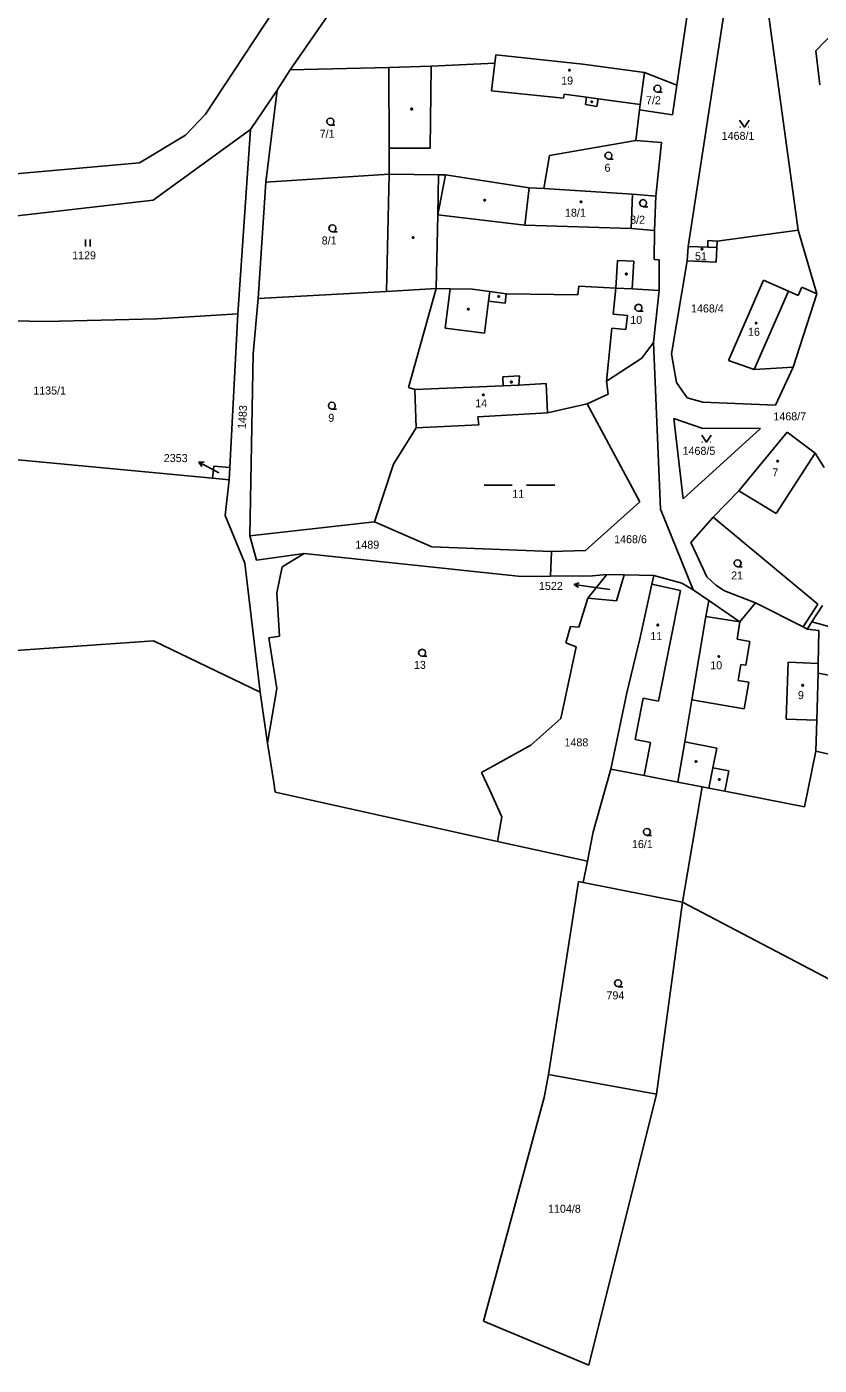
# Model space of a CAD drawing. Extents: x -852001 to -842497, y -1063614 to -1052182.
# Drawn here: x -850781 to -850612.7, y -1053765.9 to -1053481.6 of the extents above; entities that cross this region are included whole.
import ezdxf

# ---------------------------------------------------------------- set-up
doc = ezdxf.new("R2010")
doc.units = 0
for name, color, linetype in [('Default', 7, 'Continuous'), ('KN_HRANICE', 7, 'Continuous'), ('KN_KULTURY', 7, 'Continuous'), ('KN_PARCELY', 7, 'Continuous'), ('KN_SLUCKY', 7, 'Continuous')]:
    doc.layers.add(name, color=color, linetype=linetype)

# ---------------------------------------------------------------- blocks, each defined once
blk = doc.blocks.new('304')
at = {"layer": 'Default'}
blk.add_lwpolyline([(0, 0), (-0.38, 0.1), (-0.65, 0.37), (-0.75, 0.74), (-0.65, 1.11), (-0.38, 1.38), (-0.01, 1.48), (0.36, 1.38), (0.63, 1.11), (0.73, 0.73), (0.63, 0.35), (0.36, 0.08), (-0.02, -0.02), (0.98, -0.02)], dxfattribs=at)
blk = doc.blocks.new('306')
at = {"layer": 'Default'}
for p, q in [((-0.5, 1.5), (-0.5, 0)), ((0.5, 0), (0.5, 1.5))]:
    blk.add_line(p, q, dxfattribs=at)
blk = doc.blocks.new('314')
at = {"layer": 'Default'}
for p, q in [((-0.95, 0), (-0.85, 0)), ((0.85, 0), (0.95, 0))]:
    blk.add_line(p, q, dxfattribs=at)
blk.add_lwpolyline([(-1, 1.5), (0, 0), (1, 1.5)], dxfattribs=at)
blk = doc.blocks.new('803')
at = {"layer": 'Default'}
for p, q in [((-7.5, 0), (-1.5, 0)), ((1.5, 0), (7.5, 0))]:
    blk.add_line(p, q, dxfattribs=at)
blk = doc.blocks.new('10292')
at = {"layer": 'Default'}
blk.add_line((0, 3), (0, 0), dxfattribs=at)
blk.add_lwpolyline([(-0.5, 2), (0, 3), (0.5, 2)], dxfattribs=at)
blk = doc.blocks.new('402')
at = {"layer": 'Default'}
blk.add_lwpolyline([(0.09, 0.15), (0.18, 0), (0.09, -0.15), (-0.09, -0.15), (-0.18, 0), (-0.09, 0.15), (0.09, 0.15)], dxfattribs=at)

msp = doc.modelspace()

# ---------------------------------------------------------------- linework, layer by layer
at = {"layer": 'KN_HRANICE'}
for p, q in [((-850725.03, -1053490.78), (-850702.85, -1053458.77)), ((-850720.89, -1053466.48), (-850743, -1053500.2)), ((-850638.85, -1053466.06), (-850642.9, -1053493.99)), ((-850624.21, -1053473.39), (-850617.15, -1053524.78)), ((-850632.5, -1053476.14), (-850640.52, -1053528.25)), ((-850609.81, -1053482.98), (-850613.39, -1053486.7)), ((-850681.39, -1053487.58), (-850681.6, -1053489.34)), ((-850662.9, -1053489.55), (-850681.39, -1053487.58)), ((-850613.39, -1053486.7), (-850612.58, -1053493.95)), ((-850727.77, -1053495.08), (-850725.03, -1053490.78)), ((-850704.11, -1053490.22), (-850725.03, -1053490.78)), ((-850695.07, -1053489.98), (-850704.11, -1053490.22)), ((-850704, -1053507.36), (-850704.11, -1053490.22)), ((-850695.07, -1053489.98), (-850681.6, -1053489.34)), ((-850649.81, -1053491.29), (-850662.9, -1053489.55)), ((-850650.72, -1053498.08), (-850649.81, -1053491.29)), ((-850649.81, -1053491.29), (-850642.9, -1053493.99)), ((-850733.45, -1053503.39), (-850727.77, -1053495.08)), ((-850727.77, -1053495.08), (-850730.2, -1053514.63)), ((-850642.9, -1053493.99), (-850643.82, -1053500.3)), ((-850651.6, -1053505.78), (-850650.88, -1053499.27)), ((-850650.88, -1053499.27), (-850650.72, -1053498.08)), ((-850650.88, -1053499.27), (-850643.82, -1053500.3)), ((-850743, -1053500.2), (-850747.27, -1053504.66)), ((-850747.27, -1053504.66), (-850757.05, -1053510.53)), ((-850754.1, -1053518.43), (-850733.45, -1053503.39)), ((-850736.12, -1053542.56), (-850733.45, -1053503.39)), ((-850703.97, -1053512.92), (-850704, -1053507.36)), ((-850651.6, -1053505.78), (-850669.93, -1053508.92)), ((-850646.16, -1053506.15), (-850651.6, -1053505.78)), ((-850647.39, -1053517.55), (-850646.16, -1053506.15)), ((-850757.05, -1053510.53), (-850788.26, -1053513.24)), ((-850669.93, -1053508.92), (-850671.13, -1053515.98)), ((-850730.2, -1053514.63), (-850703.97, -1053512.92)), ((-850703.97, -1053512.92), (-850704.59, -1053537.84)), ((-850703.97, -1053512.92), (-850693.51, -1053513.03)), ((-850693.51, -1053513.03), (-850692.06, -1053513.04)), ((-850692.06, -1053513.04), (-850674.27, -1053515.78)), ((-850730.2, -1053514.63), (-850731.83, -1053539.3)), ((-850674.27, -1053515.78), (-850671.13, -1053515.98)), ((-850671.13, -1053515.98), (-850652.32, -1053517.19)), ((-850787.65, -1053522.28), (-850754.1, -1053518.43)), ((-850652.32, -1053517.19), (-850652.6, -1053524.47)), ((-850652.32, -1053517.19), (-850647.39, -1053517.55)), ((-850647.68, -1053524.87), (-850647.39, -1053517.55)), ((-850652.6, -1053524.47), (-850647.68, -1053524.87)), ((-850647.72, -1053531.05), (-850647.68, -1053524.87)), ((-850634.37, -1053527.13), (-850617.15, -1053524.78)), ((-850617.15, -1053524.78), (-850613.2, -1053538.34)), ((-850636.31, -1053527.03), (-850636.37, -1053528.43)), ((-850636.31, -1053527.03), (-850634.37, -1053527.13)), ((-850634.44, -1053528.52), (-850634.37, -1053527.13)), ((-850640.72, -1053531.35), (-850640.52, -1053528.25)), ((-850640.52, -1053528.25), (-850636.37, -1053528.43)), ((-850634.59, -1053531.62), (-850634.44, -1053528.52)), ((-850646.65, -1053531.12), (-850647.72, -1053531.05)), ((-850646.66, -1053537.61), (-850646.65, -1053531.12)), ((-850644.03, -1053551.05), (-850640.72, -1053531.35)), ((-850640.72, -1053531.35), (-850634.59, -1053531.62)), ((-850624.54, -1053535.45), (-850631.98, -1053552.46)), ((-850619.2, -1053537.77), (-850624.54, -1053535.45)), ((-850731.83, -1053539.3), (-850704.59, -1053537.84)), ((-850704.59, -1053537.84), (-850694.04, -1053537.19)), ((-850694.04, -1053537.19), (-850699.87, -1053558.24)), ((-850694.04, -1053537.19), (-850691.08, -1053537.27)), ((-850691.08, -1053537.27), (-850686.4, -1053537.34)), ((-850686.4, -1053537.34), (-850682.66, -1053537.85)), ((-850682.66, -1053537.85), (-850679.16, -1053538.32)), ((-850679.16, -1053538.32), (-850663.91, -1053538.55)), ((-850663.91, -1053538.55), (-850663.74, -1053536.68)), ((-850655.85, -1053537.11), (-850663.74, -1053536.68)), ((-850655.85, -1053537.11), (-850656.41, -1053542.64)), ((-850652.38, -1053537.3), (-850655.85, -1053537.11)), ((-850646.66, -1053537.61), (-850652.38, -1053537.3)), ((-850647.89, -1053548.68), (-850646.66, -1053537.61)), ((-850617.16, -1053538.65), (-850619.2, -1053537.77)), ((-850613.2, -1053538.34), (-850618.2, -1053553.93)), ((-850616.4, -1053536.9), (-850617.16, -1053538.65)), ((-850616.4, -1053536.9), (-850613.2, -1053538.34)), ((-850731.83, -1053539.3), (-850732.9, -1053551.1)), ((-850776.98, -1053544.19), (-850811.29, -1053543.49)), ((-850753.31, -1053543.66), (-850776.98, -1053544.19)), ((-850736.12, -1053542.56), (-850753.31, -1053543.66)), ((-850737.82, -1053575.23), (-850736.12, -1053542.56)), ((-850656.41, -1053542.64), (-850653.42, -1053542.95)), ((-850653.42, -1053542.95), (-850653.72, -1053545.93)), ((-850657.85, -1053556.86), (-850656.71, -1053545.63)), ((-850653.72, -1053545.93), (-850656.71, -1053545.63)), ((-850650.36, -1053552.02), (-850647.89, -1053548.68)), ((-850647.89, -1053548.68), (-850646.41, -1053584.08)), ((-850732.9, -1053551.1), (-850733.6, -1053589.76)), ((-850657.85, -1053556.86), (-850650.36, -1053552.02)), ((-850643.02, -1053557.16), (-850644.03, -1053551.05)), ((-850631.98, -1053552.46), (-850626.47, -1053554.4)), ((-850626.47, -1053554.4), (-850618.2, -1053553.93)), ((-850618.2, -1053553.93), (-850621.95, -1053561.95)), ((-850699.87, -1053558.24), (-850698.57, -1053558.66)), ((-850698.25, -1053566.82), (-850698.57, -1053558.66)), ((-850657.53, -1053559.65), (-850657.85, -1053556.86)), ((-850640.75, -1053560.43), (-850643.02, -1053557.16)), ((-850661.96, -1053561.72), (-850670.36, -1053563.6)), ((-850661.96, -1053561.72), (-850657.53, -1053559.65)), ((-850650.8, -1053582.53), (-850661.96, -1053561.72)), ((-850637.41, -1053561.33), (-850640.75, -1053560.43)), ((-850621.95, -1053561.95), (-850637.41, -1053561.33)), ((-850670.36, -1053563.6), (-850685.16, -1053564.49)), ((-850685.16, -1053564.49), (-850684.99, -1053566.13)), ((-850643.55, -1053564.8), (-850637.64, -1053566.88)), ((-850641.59, -1053581.86), (-850643.55, -1053564.8)), ((-850703.1, -1053574.48), (-850698.25, -1053566.82)), ((-850698.25, -1053566.82), (-850684.99, -1053566.13)), ((-850625.16, -1053566.93), (-850641.59, -1053581.86)), ((-850637.64, -1053566.88), (-850625.16, -1053566.93)), ((-850819.36, -1053570.11), (-850741.49, -1053577.51)), ((-850629.75, -1053580.2), (-850619.47, -1053567.69)), ((-850619.47, -1053567.69), (-850613.54, -1053572.2)), ((-850613.54, -1053572.2), (-850611.6, -1053575.23)), ((-850741.22, -1053574.92), (-850741.49, -1053577.51)), ((-850737.82, -1053575.23), (-850741.22, -1053574.92)), ((-850737.96, -1053577.85), (-850737.82, -1053575.23)), ((-850707.14, -1053586.78), (-850703.1, -1053574.48)), ((-850741.49, -1053577.51), (-850737.96, -1053577.85)), ((-850737.96, -1053577.85), (-850738.81, -1053585.42)), ((-850635.17, -1053585.8), (-850629.75, -1053580.2)), ((-850662.32, -1053592.86), (-850650.8, -1053582.53)), ((-850646.41, -1053584.08), (-850639.44, -1053601.2)), ((-850738.81, -1053585.42), (-850734.66, -1053595.56)), ((-850733.6, -1053589.76), (-850707.14, -1053586.78)), ((-850707.14, -1053586.78), (-850694.94, -1053592.06)), ((-850639.95, -1053591.18), (-850635.17, -1053585.8)), ((-850635.17, -1053585.8), (-850612.97, -1053604.25)), ((-850733.6, -1053589.76), (-850732.16, -1053594.91)), ((-850694.94, -1053592.06), (-850669.55, -1053593.05)), ((-850669.55, -1053593.05), (-850669.76, -1053598.34)), ((-850669.55, -1053593.05), (-850662.32, -1053592.86)), ((-850639.95, -1053591.18), (-850638.77, -1053593.71)), ((-850734.66, -1053595.56), (-850731.37, -1053622.93)), ((-850722.02, -1053593.47), (-850732.16, -1053594.91)), ((-850726.71, -1053596.35), (-850722.02, -1053593.47)), ((-850722.02, -1053593.47), (-850675.99, -1053598.41)), ((-850638.77, -1053593.71), (-850636.55, -1053598.46)), ((-850727.84, -1053601.86), (-850726.71, -1053596.35)), ((-850675.99, -1053598.41), (-850669.76, -1053598.34)), ((-850669.76, -1053598.34), (-850660.81, -1053598.24)), ((-850661.81, -1053603.01), (-850657.8, -1053597.97)), ((-850660.81, -1053598.24), (-850657.8, -1053597.97)), ((-850657.8, -1053597.97), (-850654.08, -1053598.05)), ((-850655.76, -1053603.54), (-850654.08, -1053598.05)), ((-850654.08, -1053598.05), (-850647.82, -1053598.17)), ((-850648.23, -1053600.03), (-850647.82, -1053598.17)), ((-850647.82, -1053598.17), (-850641.87, -1053599.8)), ((-850636.55, -1053598.46), (-850634.65, -1053600.2)), ((-850650.71, -1053611.35), (-850648.23, -1053600.03)), ((-850641.87, -1053599.8), (-850639.44, -1053601.2)), ((-850636.16, -1053603.46), (-850639.44, -1053601.2)), ((-850634.65, -1053600.2), (-850632.83, -1053601.39)), ((-850632.83, -1053601.39), (-850626.23, -1053603.99)), ((-850727.27, -1053611.05), (-850727.84, -1053601.86)), ((-850663.74, -1053609.12), (-850661.81, -1053603.01)), ((-850661.81, -1053603.01), (-850655.76, -1053603.54)), ((-850636.73, -1053606.84), (-850636.16, -1053603.46)), ((-850629.52, -1053608.02), (-850636.16, -1053603.46)), ((-850629.52, -1053608.02), (-850626.23, -1053603.99)), ((-850626.23, -1053603.99), (-850616.11, -1053609.04)), ((-850612.97, -1053604.25), (-850616.11, -1053609.04)), ((-850639.73, -1053624.59), (-850636.73, -1053606.84)), ((-850666.46, -1053612.48), (-850665.53, -1053608.97)), ((-850665.53, -1053608.97), (-850663.74, -1053609.12)), ((-850616.11, -1053609.04), (-850615.28, -1053609.57)), ((-850614.24, -1053607.97), (-850615.28, -1053609.57)), ((-850615.28, -1053609.57), (-850612.79, -1053609.83)), ((-850605.98, -1053610.26), (-850614.24, -1053607.97)), ((-850612.9, -1053616.89), (-850612.79, -1053609.83)), ((-850754.03, -1053612.06), (-850790.19, -1053614.59)), ((-850731.37, -1053622.93), (-850754.03, -1053612.06)), ((-850727.27, -1053611.05), (-850729.55, -1053611.4)), ((-850729.55, -1053611.4), (-850727.84, -1053622.2)), ((-850664.31, -1053613.34), (-850666.46, -1053612.48)), ((-850653.56, -1053623.08), (-850650.71, -1053611.35)), ((-850667.53, -1053628.53), (-850664.31, -1053613.34)), ((-850619.29, -1053616.58), (-850619.67, -1053628.68)), ((-850612.9, -1053616.89), (-850619.29, -1053616.58)), ((-850612.93, -1053618.93), (-850612.9, -1053616.89)), ((-850612.93, -1053618.93), (-850613.21, -1053628.86)), ((-850599.25, -1053621.58), (-850612.93, -1053618.93)), ((-850731.37, -1053622.93), (-850729.84, -1053633.77)), ((-850727.84, -1053622.2), (-850729.84, -1053633.77)), ((-850656.92, -1053639.28), (-850653.56, -1053623.08)), ((-850641.24, -1053633.53), (-850639.73, -1053624.59)), ((-850673.91, -1053634.19), (-850667.53, -1053628.53)), ((-850619.67, -1053628.68), (-850613.21, -1053628.86)), ((-850613.21, -1053628.86), (-850613.39, -1053635.48)), ((-850729.84, -1053633.77), (-850728.5, -1053642.15)), ((-850684.37, -1053639.99), (-850673.91, -1053634.19)), ((-850642.68, -1053642.07), (-850641.24, -1053633.53)), ((-850615.84, -1053647.32), (-850613.39, -1053635.48)), ((-850613.39, -1053635.48), (-850581.18, -1053642.71)), ((-850682.73, -1053643.61), (-850684.37, -1053639.99)), ((-850660.67, -1053652.62), (-850656.92, -1053639.28)), ((-850656.92, -1053639.28), (-850649.89, -1053640.66)), ((-850649.89, -1053640.66), (-850642.68, -1053642.07)), ((-850728.5, -1053642.15), (-850728.18, -1053644.2)), ((-850728.18, -1053644.2), (-850680.97, -1053654.64)), ((-850682.73, -1053643.61), (-850680.1, -1053649.45)), ((-850642.68, -1053642.07), (-850637.57, -1053643.07)), ((-850641.71, -1053667.54), (-850637.57, -1053643.07)), ((-850637.57, -1053643.07), (-850636.11, -1053643.35)), ((-850636.11, -1053643.35), (-850632.74, -1053644.01)), ((-850632.74, -1053644.01), (-850615.84, -1053647.32)), ((-850680.1, -1053649.45), (-850680.97, -1053654.64)), ((-850661.92, -1053658.86), (-850660.67, -1053652.62)), ((-850661.92, -1053658.86), (-850680.97, -1053654.64)), ((-850662.83, -1053663.39), (-850661.92, -1053658.86)), ((-850670.18, -1053704.16), (-850663.78, -1053663.19)), ((-850663.78, -1053663.19), (-850662.83, -1053663.39)), ((-850641.71, -1053667.54), (-850662.83, -1053663.39)), ((-850647.22, -1053708.36), (-850641.71, -1053667.54)), ((-850641.71, -1053667.54), (-850585.08, -1053697.36)), ((-850671.08, -1053709.08), (-850670.18, -1053704.16)), ((-850647.22, -1053708.36), (-850670.18, -1053704.16)), ((-850683.99, -1053756.59), (-850671.08, -1053709.08)), ((-850661.58, -1053765.92), (-850647.22, -1053708.36)), ((-850661.58, -1053765.92), (-850683.99, -1053756.59))]:
    msp.add_line(p, q, dxfattribs=at)
at = {"layer": 'KN_PARCELY'}
for p, q in [((-850740.16, -1053576.38), (-850741.76, -1053575.51)), ((-850657.18, -1053601.12), (-850661.75, -1053600.48))]:
    msp.add_line(p, q, dxfattribs=at)
at = {"layer": 'KN_SLUCKY'}
for p, q in [((-850695.07, -1053489.98), (-850695.27, -1053507.36)), ((-850681.6, -1053489.34), (-850682.31, -1053495.23)), ((-850682.31, -1053495.23), (-850666.96, -1053496.77)), ((-850666.87, -1053495.92), (-850666.96, -1053496.77)), ((-850666.87, -1053495.92), (-850662.07, -1053496.56)), ((-850662.07, -1053496.56), (-850662.33, -1053498.14)), ((-850662.07, -1053496.56), (-850659.66, -1053496.88)), ((-850659.93, -1053498.53), (-850662.33, -1053498.14)), ((-850659.66, -1053496.88), (-850659.93, -1053498.53)), ((-850659.66, -1053496.88), (-850650.72, -1053498.08)), ((-850695.27, -1053507.36), (-850704, -1053507.36)), ((-850693.65, -1053521.56), (-850693.51, -1053513.03)), ((-850693.65, -1053521.56), (-850692.06, -1053513.04)), ((-850674.27, -1053515.78), (-850675.21, -1053523.73)), ((-850694.04, -1053537.19), (-850693.65, -1053521.56)), ((-850693.65, -1053521.56), (-850675.21, -1053523.73)), ((-850675.21, -1053523.73), (-850652.6, -1053524.47)), ((-850636.37, -1053528.43), (-850634.44, -1053528.52)), ((-850655.53, -1053531.23), (-850655.85, -1053537.11)), ((-850655.53, -1053531.23), (-850652.07, -1053531.41)), ((-850652.38, -1053537.3), (-850652.07, -1053531.41)), ((-850691.08, -1053537.27), (-850692.14, -1053545.65)), ((-850682.66, -1053537.85), (-850682.92, -1053539.86)), ((-850679.16, -1053538.32), (-850679.35, -1053540.32)), ((-850619.2, -1053537.77), (-850626.47, -1053554.4)), ((-850682.92, -1053539.86), (-850683.79, -1053546.71)), ((-850679.35, -1053540.32), (-850682.92, -1053539.86)), ((-850683.79, -1053546.71), (-850692.14, -1053545.65)), ((-850679.9, -1053555.97), (-850676.31, -1053555.78)), ((-850679.82, -1053557.89), (-850679.9, -1053555.97)), ((-850676.44, -1053557.75), (-850676.31, -1053555.78)), ((-850698.57, -1053558.66), (-850679.82, -1053557.89)), ((-850679.82, -1053557.89), (-850676.44, -1053557.75)), ((-850670.7, -1053557.4), (-850676.44, -1053557.75)), ((-850670.36, -1053563.6), (-850670.7, -1053557.4)), ((-850621.84, -1053585), (-850613.54, -1053572.2)), ((-850629.75, -1053580.2), (-850621.84, -1053585)), ((-850648.23, -1053600.03), (-850642.17, -1053601.32)), ((-850646.79, -1053624.87), (-850642.17, -1053601.32)), ((-850612.02, -1053604.55), (-850614.24, -1053607.97)), ((-850636.73, -1053606.84), (-850629.52, -1053608.02)), ((-850629.52, -1053608.02), (-850630.13, -1053611.69)), ((-850627.43, -1053612.17), (-850630.13, -1053611.69)), ((-850627.43, -1053612.17), (-850628.28, -1053617.21)), ((-850629.33, -1053617.04), (-850629.9, -1053620.46)), ((-850628.28, -1053617.21), (-850629.33, -1053617.04)), ((-850629.9, -1053620.46), (-850627.64, -1053620.84)), ((-850627.64, -1053620.84), (-850628.59, -1053626.47)), ((-850651.76, -1053632.99), (-850650.04, -1053624.23)), ((-850650.04, -1053624.23), (-850646.79, -1053624.87)), ((-850628.59, -1053626.47), (-850639.73, -1053624.59)), ((-850648.51, -1053633.63), (-850651.76, -1053632.99)), ((-850649.89, -1053640.66), (-850648.51, -1053633.63)), ((-850641.24, -1053633.53), (-850634.45, -1053634.86)), ((-850634.45, -1053634.86), (-850635.27, -1053639.02)), ((-850635.27, -1053639.02), (-850636.11, -1053643.35))]:
    msp.add_line(p, q, dxfattribs=at)
msp.add_lwpolyline([(-850635.27, -1053639.02), (-850631.89, -1053639.68), (-850632.74, -1053644.01)], dxfattribs=at)

# ---------------------------------------------------------------- block references
at = {"layer": 'KN_KULTURY'}
for name, p in [('402', (-850665.71, -1053490.82)), ('304', (-850647.02, -1053495.49)), ('402', (-850699.23, -1053499.06)), ('402', (-850660.97, -1053497.53)), ('304', (-850716.49, -1053502.48)), ('314', (-850628.58, -1053502.92)), ('304', (-850657.43, -1053509.7)), ('402', (-850683.74, -1053518.46)), ('402', (-850663.26, -1053518.77)), ('304', (-850650.08, -1053519.8)), ('304', (-850716.06, -1053525.15)), ('306', (-850768, -1053528.3)), ('402', (-850698.92, -1053526.37)), ('402', (-850637.59, -1053528.85)), ('402', (-850653.63, -1053534.11)), ('402', (-850680.76, -1053538.87)), ('402', (-850687.21, -1053541.57)), ('304', (-850651.06, -1053542.02)), ('402', (-850626.07, -1053544.55)), ('402', (-850678.05, -1053557.06)), ('304', (-850716.17, -1053562.82)), ('402', (-850684.02, -1053559.79)), ('314', (-850636.64, -1053569.83)), ('402', (-850621.52, -1053573.87)), ('803', (-850676.36, -1053578.94)), ('304', (-850630, -1053596.3)), ('402', (-850646.96, -1053608.67)), ('304', (-850697, -1053615.3)), ('402', (-850634.01, -1053615.36)), ('402', (-850616.21, -1053621.49)), ('402', (-850638.84, -1053637.68)), ('402', (-850633.91, -1053641.51)), ('304', (-850649.25, -1053653.36)), ('304', (-850655.39, -1053685.5))]:
    msp.add_blockref(name, p, dxfattribs=at)
at = {"layer": 'KN_PARCELY'}
for p, rotation in [((-850741.76, -1053575.51), 61.36378000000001), ((-850661.75, -1053600.48), 81.99025999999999)]:
    msp.add_blockref('10292', p, dxfattribs=dict(at, rotation=rotation))

# ---------------------------------------------------------------- texts
for s, height, p in [('19', 1.7, (-850667.48, -1053493.87)), ('7/2', 1.7, (-850649.47, -1053498.06)), ('7/1', 1.7, (-850718.76, -1053505.18)), ('1468/1', 1.7, (-850633.4, -1053505.62)), ('6', 1.7, (-850658.28, -1053512.4)), ('18/1', 1.7, (-850666.67, -1053521.95)), ('8/2', 1.7, (-850652.84, -1053523.44)), ('8/1', 1.7, (-850718.33, -1053527.85)), ('1129', 1.7, (-850771.32, -1053531)), ('51', 1.7, (-850639.06, -1053531.18)), ('1468/4', 1.7, (-850639.91, -1053542.29)), ('10', 1.7, (-850652.8, -1053544.72)), ('16', 1.7, (-850627.81, -1053547.25)), ('1135/1', 1.7, (-850779.58, -1053559.72)), ('14', 1.7, (-850685.73, -1053562.43)), ('9', 1.7, (-850716.94, -1053565.52)), ('1468/7', 1.7, (-850622.42, -1053565.21)), ('2353', 1.7, (-850751.86, -1053574.07)), ('1468/5', 1.7, (-850641.7, -1053572.53)), ('7', 1.7, (-850622.64, -1053577.11)), ('2353', 0.1, (-850740.35, -1053576.38)), ('11', 1.7, (-850677.86, -1053581.64)), ('1468/6', 1.7, (-850656.23, -1053591.31)), ('1489', 1.7, (-850711.18, -1053592.47)), ('21', 1.7, (-850631.38, -1053599)), ('1522', 1.7, (-850672.19, -1053601.23)), ('1522', 0.1, (-850657.38, -1053601.12)), ('11', 1.7, (-850648.57, -1053611.89)), ('13', 1.7, (-850698.74, -1053618)), ('10', 1.7, (-850635.81, -1053618.07)), ('9', 1.7, (-850617.21, -1053624.43)), ('1488', 1.7, (-850666.77, -1053634.46)), ('16/1', 1.7, (-850652.45, -1053656.06)), ('794', 1.7, (-850657.86, -1053688.2)), ('1104/8', 1.7, (-850670.27, -1053733.53))]:
    msp.add_text(s, height=height, dxfattribs=at).set_placement(p)
msp.add_text('1483', height=1.7, rotation=86.116, dxfattribs=at).set_placement((-850734.49, -1053567.09))

doc.saveas('drawing.dxf')
